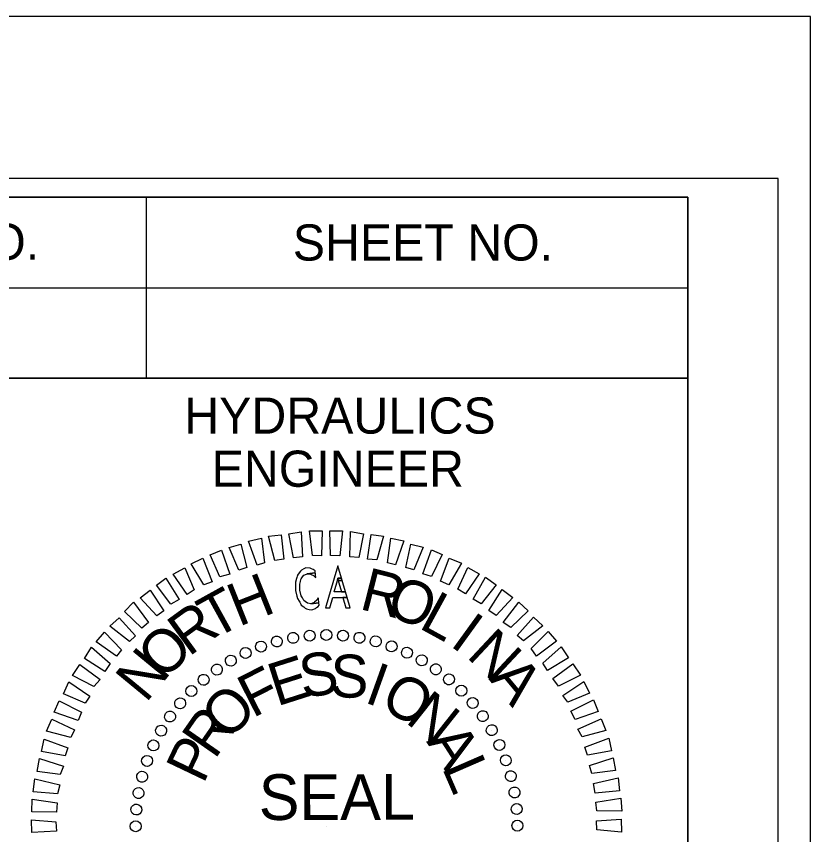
# Model space of a CAD drawing. Extents: x 2331575 to 2333259, y 609001 to 610101.
# Drawn here: x 2333149.3 to 2333259.2, y 609988.3 to 610101.5 of the extents above; entities that cross this region are included whole.
import ezdxf

# ---------------------------------------------------------------- set-up
doc = ezdxf.new("R2010")
doc.units = 0
for name, color, linetype in [('Default', 7, 'Continuous'), ('Sheet Cutting Line CELL', 7, 'Continuous'), ('Sheet Plot Border Inside CELL', 7, 'Continuous'), ('Sheet Plot Border Outside CELL', 7, 'Continuous'), ('Sheet Profile CELL', 7, 'Continuous')]:
    doc.layers.add(name, color=color, linetype=linetype)

msp = doc.modelspace()

# ---------------------------------------------------------------- linework, layer by layer
at = {"layer": 'Default'}
for p, q in [((2333187.57, 610015.45), (2333187.57, 610015.45)), ((2333187.57, 610015.45), (2333187.57, 610015.45)), ((2333189.83, 610015.81), (2333189.83, 610015.81)), ((2333189.83, 610015.81), (2333189.83, 610015.81)), ((2333192.15, 610015.9), (2333192.15, 610015.9)), ((2333192.15, 610015.9), (2333192.15, 610015.9)), ((2333194.47, 610015.79), (2333194.47, 610015.79)), ((2333194.47, 610015.79), (2333194.47, 610015.79)), ((2333196.74, 610015.46), (2333196.74, 610015.46)), ((2333196.74, 610015.46), (2333196.74, 610015.46)), ((2333183.11, 610014.31), (2333183.11, 610014.31)), ((2333183.11, 610014.31), (2333183.11, 610014.31)), ((2333185.32, 610014.99), (2333185.32, 610014.99)), ((2333185.32, 610014.99), (2333185.32, 610014.99)), ((2333199.02, 610015.03), (2333199.02, 610015.03)), ((2333199.02, 610015.03), (2333199.02, 610015.03)), ((2333201.24, 610014.34), (2333201.24, 610014.34)), ((2333201.24, 610014.34), (2333201.24, 610014.34)), ((2333180.97, 610013.43), (2333180.97, 610013.43)), ((2333180.97, 610013.43), (2333180.97, 610013.43)), ((2333203.31, 610013.43), (2333203.31, 610013.43)), ((2333203.31, 610013.43), (2333203.31, 610013.43)), ((2333178.99, 610012.34), (2333178.99, 610012.34)), ((2333178.99, 610012.34), (2333178.99, 610012.34)), ((2333205.44, 610012.41), (2333205.44, 610012.41)), ((2333205.44, 610012.41), (2333205.44, 610012.41)), ((2333176.96, 610011.09), (2333176.96, 610011.09)), ((2333176.96, 610011.09), (2333176.96, 610011.09)), ((2333207.31, 610011.13), (2333207.31, 610011.13)), ((2333207.31, 610011.13), (2333207.31, 610011.13)), ((2333175.19, 610009.74), (2333175.19, 610009.74)), ((2333175.19, 610009.74), (2333175.19, 610009.74)), ((2333209.23, 610009.75), (2333209.23, 610009.75)), ((2333209.23, 610009.75), (2333209.23, 610009.75)), ((2333173.48, 610008.12), (2333173.48, 610008.12)), ((2333173.48, 610008.12), (2333173.48, 610008.12)), ((2333210.9, 610008.19), (2333210.9, 610008.19)), ((2333210.9, 610008.19), (2333210.9, 610008.19)), ((2333171.93, 610006.46), (2333171.93, 610006.46)), ((2333171.93, 610006.46), (2333171.93, 610006.46)), ((2333212.51, 610006.43), (2333212.51, 610006.43)), ((2333212.51, 610006.43), (2333212.51, 610006.43)), ((2333170.49, 610004.59), (2333170.49, 610004.59)), ((2333170.49, 610004.59), (2333170.49, 610004.59)), ((2333213.86, 610004.67), (2333213.86, 610004.67)), ((2333213.86, 610004.67), (2333213.86, 610004.67)), ((2333169.21, 610002.67), (2333169.21, 610002.67)), ((2333169.21, 610002.67), (2333169.21, 610002.67)), ((2333215.11, 610002.69), (2333215.11, 610002.69)), ((2333215.11, 610002.69), (2333215.11, 610002.69)), ((2333168.2, 610000.59), (2333168.2, 610000.59)), ((2333168.2, 610000.59), (2333168.2, 610000.59)), ((2333216.15, 610000.65), (2333216.15, 610000.65)), ((2333216.15, 610000.65), (2333216.15, 610000.65)), ((2333167.29, 609998.47), (2333167.29, 609998.47)), ((2333167.29, 609998.47), (2333167.29, 609998.47)), ((2333217.03, 609998.56), (2333217.03, 609998.56)), ((2333217.03, 609998.56), (2333217.03, 609998.56)), ((2333166.6, 609996.24), (2333166.6, 609996.24)), ((2333166.6, 609996.24), (2333166.6, 609996.24)), ((2333217.76, 609996.36), (2333217.76, 609996.36)), ((2333217.76, 609996.36), (2333217.76, 609996.36)), ((2333166.16, 609994.02), (2333166.16, 609994.02)), ((2333166.16, 609994.02), (2333166.16, 609994.02)), ((2333218.22, 609994.05), (2333218.22, 609994.05)), ((2333218.22, 609994.05), (2333218.22, 609994.05)), ((2333165.89, 609991.69), (2333165.89, 609991.69)), ((2333165.89, 609991.69), (2333165.89, 609991.69)), ((2333218.58, 609991.8), (2333218.58, 609991.8)), ((2333218.58, 609991.8), (2333218.58, 609991.8)), ((2333192.23, 609989.45), (2333192.23, 609989.45)), ((2333192.23, 609989.45), (2333192.23, 609989.45)), ((2333218.68, 609989.48), (2333218.68, 609989.48)), ((2333218.68, 609989.48), (2333218.68, 609989.48)), ((2333165.78, 609989.38), (2333165.78, 609989.38)), ((2333165.78, 609989.38), (2333165.78, 609989.38))]:
    msp.add_line(p, q, dxfattribs=at)
for points in [[(2333187.63, 610026.57), (2333186.98, 610029.87), (2333188.72, 610030.17), (2333188.89, 610026.7)], [(2333190.26, 610026.88), (2333189.87, 610030.3), (2333191.61, 610030.28), (2333191.52, 610026.85)], [(2333192.78, 610026.88), (2333192.67, 610030.3), (2333194.4, 610030.28), (2333194.05, 610026.85)], [(2333195.42, 610026.71), (2333195.51, 610030.19), (2333197.31, 610029.86), (2333196.69, 610026.58)], [(2333182.59, 610025.52), (2333181.42, 610028.87), (2333183.2, 610029.28), (2333183.64, 610025.86)], [(2333185.05, 610026.2), (2333184.2, 610029.56), (2333185.93, 610029.75), (2333186.31, 610026.39)], [(2333197.9, 610026.39), (2333198.37, 610029.77), (2333200.11, 610029.54), (2333199.17, 610026.26)], [(2333200.65, 610025.87), (2333201.12, 610029.3), (2333202.91, 610028.91), (2333201.77, 610025.57)], [(2333180.07, 610024.85), (2333178.75, 610027.98), (2333180.37, 610028.43), (2333181.17, 610025.23)], [(2333203.19, 610025.23), (2333203.87, 610028.45), (2333205.57, 610028.01), (2333204.31, 610024.88)], [(2333177.45, 610023.95), (2333176.08, 610026.98), (2333177.65, 610027.64), (2333178.81, 610024.3)], [(2333205.53, 610024.32), (2333206.73, 610027.67), (2333208.22, 610027.01), (2333206.75, 610023.98)], [(2333175.21, 610022.8), (2333173.47, 610025.72), (2333175.09, 610026.49), (2333176.36, 610023.25)], [(2333207.98, 610023.32), (2333209.18, 610026.5), (2333210.88, 610025.8), (2333209.14, 610022.81)], [(2333172.92, 610021.49), (2333170.97, 610024.3), (2333172.58, 610025.18), (2333173.9, 610022.15)], [(2333189.79, 610019.43), (2333190.18, 610019.38), (2333190.7, 610019.55), (2333190.84, 610019.67), (2333191.05, 610019.84), (2333191.2, 610020.03), (2333191.16, 610020.34), (2333191.16, 610020.35), (2333190.03, 610020.2), (2333189.62, 610020.27), (2333189.56, 610020.28), (2333189.27, 610020.5), (2333189.08, 610020.65), (2333188.88, 610021.02), (2333188.71, 610021.32), (2333188.52, 610022.1), (2333188.52, 610022.1), (2333188.51, 610022.93), (2333188.59, 610023.26), (2333188.67, 610023.57), (2333188.69, 610023.64), (2333188.9, 610023.92), (2333189.06, 610024.14), (2333189.21, 610024.2), (2333189.54, 610024.34), (2333190.66, 610024.49), (2333190.66, 610024.49), (2333190.63, 610024.75), (2333190.37, 610024.94), (2333190.12, 610025.05), (2333189.93, 610025.14), (2333189.36, 610025.16), (2333189.07, 610025.02), (2333188.73, 610024.87), (2333188.61, 610024.72), (2333188.42, 610024.46), (2333188.2, 610024.17), (2333188.2, 610024.17), (2333188.17, 610024.07), (2333188.15, 610024.02), (2333188.1, 610023.82), (2333188.02, 610023.55), (2333188, 610023.49), (2333187.92, 610023.18), (2333187.92, 610022.85), (2333187.92, 610022.03), (2333187.92, 610022.02), (2333188.12, 610021.25), (2333188.2, 610020.93), (2333188.41, 610020.57), (2333188.51, 610020.4), (2333188.64, 610020.16), (2333188.65, 610020.14), (2333188.72, 610020.03), (2333188.72, 610020.02), (2333189.07, 610019.76), (2333189.26, 610019.61), (2333189.42, 610019.49)], [(2333190.66, 610023.89), (2333190.72, 610023.84), (2333190.72, 610023.9), (2333190.69, 610024.15), (2333190.67, 610024.34), (2333190.67, 610024.34), (2333190.67, 610024.39), (2333190.66, 610024.49), (2333189.54, 610024.34), (2333190.01, 610024.31), (2333190.09, 610024.27), (2333190.4, 610024.12)], [(2333192.48, 610021.08), (2333192.05, 610019.64), (2333192.66, 610019.65), (2333193.07, 610021.08), (2333195.06, 610021.08), (2333194.84, 610021.84), (2333193.28, 610021.83), (2333193.64, 610023.1), (2333193.64, 610023.1), (2333193.72, 610023.42), (2333193.72, 610023.43), (2333193.77, 610023.73), (2333194.27, 610023.73), (2333193.76, 610025.43), (2333193.26, 610023.73), (2333193.17, 610023.43), (2333193.17, 610023.42), (2333193.08, 610023.1), (2333193.07, 610023.1), (2333192.7, 610021.83)], [(2333210.37, 610022.2), (2333211.78, 610025.23), (2333213.33, 610024.36), (2333211.43, 610021.59)], [(2333170.68, 610020.13), (2333168.67, 610022.79), (2333169.98, 610023.76), (2333171.82, 610020.79)], [(2333193.77, 610023.73), (2333193.83, 610023.43), (2333194.36, 610023.43), (2333194.27, 610023.73)], [(2333193.91, 610023.1), (2333194.27, 610021.83), (2333194.84, 610021.84), (2333194.46, 610023.1), (2333194.46, 610023.1), (2333194.36, 610023.42), (2333194.36, 610023.43), (2333193.83, 610023.43), (2333193.83, 610023.42), (2333193.91, 610023.1)], [(2333212.5, 610020.82), (2333214.23, 610023.86), (2333215.68, 610022.83), (2333213.62, 610020.21)], [(2333168.7, 610018.52), (2333166.39, 610021.01), (2333167.79, 610022.08), (2333169.69, 610019.22)], [(2333214.69, 610019.28), (2333216.53, 610022.16), (2333217.98, 610021.08), (2333215.7, 610018.56)], [(2333166.63, 610016.84), (2333164.26, 610019.12), (2333165.5, 610020.41), (2333167.56, 610017.6)], [(2333190.51, 610020.38), (2333190.03, 610020.2), (2333191.16, 610020.35), (2333191.15, 610020.46), (2333191.15, 610020.48), (2333191.11, 610020.73), (2333191.09, 610020.91), (2333191.07, 610021.04), (2333191.07, 610021.04), (2333190.98, 610020.9), (2333190.85, 610020.7), (2333190.53, 610020.4)], [(2333194.47, 610021.08), (2333194.88, 610019.65), (2333195.49, 610019.65), (2333195.06, 610021.08)], [(2333216.67, 610017.63), (2333218.83, 610020.41), (2333220.12, 610019.23), (2333217.74, 610016.91)], [(2333164.92, 610014.97), (2333162.2, 610017.08), (2333163.49, 610018.26), (2333165.75, 610015.78)], [(2333218.6, 610015.82), (2333220.87, 610018.34), (2333222.16, 610017.16), (2333219.46, 610015.05)], [(2333163.12, 610012.93), (2333160.34, 610014.93), (2333161.47, 610016.27), (2333163.84, 610013.84)], [(2333220.53, 610014.02), (2333222.91, 610016.38), (2333224.04, 610015.03), (2333221.29, 610012.97)], [(2333161.52, 610010.85), (2333158.7, 610012.64), (2333159.67, 610014.18), (2333162.24, 610011.92)], [(2333222.15, 610011.99), (2333224.69, 610014.25), (2333225.72, 610012.74), (2333222.8, 610010.95)], [(2333159.98, 610008.76), (2333157.05, 610010.29), (2333158.08, 610011.78), (2333160.86, 610009.73)], [(2333223.56, 610009.86), (2333226.32, 610011.91), (2333227.35, 610010.3), (2333224.32, 610008.82)], [(2333158.81, 610006.47), (2333155.78, 610007.74), (2333156.54, 610009.38), (2333159.43, 610007.43)], [(2333224.92, 610007.51), (2333227.84, 610009.46), (2333228.61, 610007.84), (2333225.63, 610006.58)], [(2333157.81, 610004.03), (2333154.52, 610005.18), (2333155.22, 610006.78), (2333158.31, 610005.2)], [(2333226.02, 610005.32), (2333229.15, 610006.91), (2333229.81, 610005.29), (2333226.62, 610004.17)], [(2333156.8, 610001.69), (2333153.46, 610002.58), (2333154.17, 610004.23), (2333157.3, 610002.76)], [(2333227.01, 610002.86), (2333230.25, 610004.29), (2333230.86, 610002.67), (2333227.61, 610001.77)], [(2333156.05, 609999.15), (2333152.77, 609999.77), (2333153.11, 610001.47), (2333156.4, 610000.26)], [(2333227.96, 610000.35), (2333231.3, 610001.62), (2333231.65, 609999.84), (2333228.35, 609999.25)], [(2333155.36, 609996.56), (2333152.14, 609996.97), (2333152.48, 609998.77), (2333155.82, 609997.73)], [(2333228.63, 609997.83), (2333231.88, 609998.9), (2333232.23, 609997.11), (2333228.92, 609996.73)], [(2333154.99, 609993.91), (2333151.62, 609994.17), (2333151.85, 609995.96), (2333155.29, 609995.13)], [(2333229.16, 609995.31), (2333232.57, 609996.12), (2333232.76, 609994.33), (2333229.39, 609994)], [(2333154.83, 609991.38), (2333151.4, 609991.42), (2333151.48, 609993.17), (2333154.91, 609992.65)], [(2333229.47, 609992.74), (2333232.94, 609993.28), (2333233.08, 609991.49), (2333229.65, 609991.53)], [(2333154.83, 609988.75), (2333151.41, 609988.53), (2333151.37, 609990.32), (2333154.75, 609990.01)], [(2333229.57, 609990.16), (2333232.99, 609990.38), (2333233.03, 609988.59), (2333229.65, 609988.9)]]:
    msp.add_lwpolyline(points, close=True, dxfattribs=at)
for centre, major_axis in [((2333189.87, 610015.78), (-0.067, 0.756)), ((2333192.18, 610015.89), (-0.001, 0.759)), ((2333194.48, 610015.79), (0.065, 0.756)), ((2333185.34, 610014.98), (-0.197, 0.733)), ((2333187.59, 610015.48), (-0.133, 0.747)), ((2333196.77, 610015.49), (0.131, 0.747)), ((2333199.02, 610015), (0.195, 0.733)), ((2333183.14, 610014.28), (-0.26, 0.713)), ((2333201.22, 610014.31), (0.258, 0.713)), ((2333178.97, 610012.33), (-0.38, 0.656)), ((2333181.01, 610013.4), (-0.322, 0.687)), ((2333203.35, 610013.43), (0.32, 0.688)), ((2333205.39, 610012.37), (0.378, 0.658)), ((2333177.03, 610011.09), (-0.436, 0.621)), ((2333207.34, 610011.13), (0.434, 0.622)), ((2333175.2, 610009.68), (-0.488, 0.58)), ((2333209.17, 610009.73), (0.487, 0.582)), ((2333173.5, 610008.12), (-0.537, 0.536)), ((2333210.87, 610008.17), (0.536, 0.537)), ((2333171.95, 610006.42), (-0.582, 0.487)), ((2333212.43, 610006.48), (0.58, 0.488)), ((2333170.55, 610004.59), (-0.622, 0.434)), ((2333213.84, 610004.65), (0.621, 0.436)), ((2333169.31, 610002.64), (-0.658, 0.378)), ((2333215.08, 610002.71), (0.656, 0.38)), ((2333168.25, 610000.6), (-0.688, 0.32)), ((2333216.15, 610000.66), (0.687, 0.322)), ((2333167.37, 609998.46), (-0.713, 0.258)), ((2333217.03, 609998.54), (0.713, 0.26)), ((2333166.68, 609996.27), (-0.733, 0.195)), ((2333217.73, 609996.34), (0.733, 0.197)), ((2333166.18, 609994.01), (-0.747, 0.131)), ((2333218.23, 609994.09), (0.747, 0.133)), ((2333165.89, 609991.73), (-0.756, 0.065)), ((2333218.54, 609991.8), (0.756, 0.067)), ((2333165.79, 609989.42), (-0.759, -0.001)), ((2333218.64, 609989.5), (0.759, 0.001))]:
    msp.add_ellipse(centre, major_axis=major_axis, ratio=0.999708, dxfattribs=at)
at = {"layer": 'Sheet Cutting Line CELL'}
msp.add_line((2333259.23, 610101.48), (2331575.23, 610101.48), dxfattribs=at)
at = {"layer": 'Sheet Plot Border Inside CELL'}
msp.add_lwpolyline([(2331588.23, 609023.93), (2333254.73, 609023.93), (2333254.73, 610079.03), (2331588.23, 610079.03)], close=True, dxfattribs=at)
at = {"layer": 'Sheet Plot Border Outside CELL'}
msp.add_lwpolyline([(2331575.23, 609001.48), (2333259.23, 609001.48), (2333259.23, 610101.48), (2331575.23, 610101.48)], close=True, dxfattribs=at)
at = {"layer": 'Sheet Profile CELL'}
for p, q in [((2333167.23, 610076.43), (2333167.23, 610051.43)), ((2333042.18, 610063.93), (2333242.23, 610063.93))]:
    msp.add_line(p, q, dxfattribs=at)
for points in [[(2333242.23, 610076.48), (2331742.23, 610076.48), (2331742.23, 609026.48), (2333242.23, 609026.48)], [(2333042.18, 610076.48), (2333242.23, 610076.48), (2333242.23, 610051.43), (2333042.18, 610051.43)], [(2333142.23, 610051.43), (2333242.23, 610051.43), (2333242.23, 609938.93), (2333142.23, 609938.93)]]:
    msp.add_lwpolyline(points, close=True, dxfattribs=at)

# ---------------------------------------------------------------- texts
at = {"layer": 'Default'}
for s, height, rotation, p in [('R', 5.94, 345.7021, (2333196.61, 610019.52)), ('H', 5.94, 21.7004, (2333180.06, 610016.99)), ('O', 5.94, 338.5021, (2333200.16, 610018.79)), ('T', 5.94, 28.9007, (2333176.62, 610015.19)), ('L', 5.94, 331.3018, (2333204.83, 610016.93)), ('R', 5.94, 36.1015, (2333173.13, 610012.8)), ('I', 5.94, 324.1011, (2333209.14, 610014.49)), ('O', 5.94, 43.3027, (2333169.56, 610009.47)), ('N', 5.94, 316.8999, (2333211.44, 610012.89)), ('N', 5.94, 50.5045, (2333167.19, 610006.37)), ('S', 5.94, 8.3366, (2333188.89, 610007.15)), ('S', 5.94, 358.9814, (2333192.68, 610007.27)), ('E', 5.94, 17.692, (2333185.33, 610005.97)), ('F', 5.94, 27.048, (2333181.98, 610004.33)), ('I', 5.94, 340.2706, (2333197.27, 610006.62)), ('A', 5.94, 309.6981, (2333214.6, 610009.79)), ('A', 5.94, 309.6981, (2333214.6, 610009.79)), ('O', 5.94, 330.9144, (2333199.39, 610005.92)), ('O', 5.94, 45.7622, (2333178.57, 610001.1)), ('N', 5.94, 321.5576, (2333202.97, 610003.88)), ('R', 5.94, 55.1206, (2333176.72, 609998.54)), ('A', 5.94, 302.8412, (2333205.97, 610001.15)), ('P', 5.94, 64.4798, (2333175.15, 609995.14)), ('L', 5.94, 293.4818, (2333208.14, 609997.55)), ('SEAL', 6.32, 0.081, (2333182.83, 609990.28))]:
    msp.add_text(s, height=height, rotation=rotation, dxfattribs=at).set_placement(p)
at = {"layer": 'Sheet Profile CELL'}
for s, height, p in [('PROJECT REFERENCE NO.', 5.0001, (2333064.39, 610067.79)), ('SHEET NO.', 5, (2333187.54, 610067.69)), ('HYDRAULICS', 5, (2333172.52, 610043.74)), ('ENGINEER', 5, (2333176.31, 610036.39))]:
    msp.add_text(s, height=height, dxfattribs=at).set_placement(p)

doc.saveas('drawing.dxf')
